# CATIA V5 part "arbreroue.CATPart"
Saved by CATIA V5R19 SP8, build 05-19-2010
Part number: arbreroue
Bounding box of the stored display mesh (mm): x -30 to 30, y -15 to 15, z -15 to 15
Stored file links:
  G:\EU_thinkMotion\CFAO_2010\SIL_groupe1\SIL_groupe1\A reprendre\scador\monocycle\arbreroue.CATPart
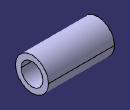
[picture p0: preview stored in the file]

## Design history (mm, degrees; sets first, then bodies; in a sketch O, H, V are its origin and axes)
Body1 (main body)
  Sketch1 on yz-plane, origin (0, 0, 0), H (0, 1, 0), V (0, 0, 1)
    circle A1 centre (0, 0) radius 15
    circle A2 centre (0, 0) radius 10
    radius A1 = 15
    distance A2 A1 = 5
    concentricity: A2 A1
  Pad1: profile Sketch1, direction (1, 0, 0), length 30, opposite side length 30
